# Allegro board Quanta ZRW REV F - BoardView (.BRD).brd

Outline 234.6 x 204.38 mm; copper layers: TOP, SVCC, IN1, IN2, SGND, BOTTOM. Coordinates in mm from the lower left corner of the outline.

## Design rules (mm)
constraint set DEFAULT: min track width 0.114
net group DFP-S3.5(4)W4.5(5)-T12B: nets VMA_RDQS4 VMA_WDQS4
net group DFP-S10W4.5(5)-T2B: nets VCORE_SENSE VCORESS_SENSE
net group W10-T12B: nets HDMI_5V RSET
net group W12-T12B: nets PCIE_RCOMPN PCIE_RCOMPP
net group W25-T12B: nets +3V_RTC VCCRTC_2
net group W50-T12B: nets +TPVDD +VDDQ_VTT
net group W60-T12B: nets LANVCC V_BLIGHT
net group W80-T12B: nets +5V_HDD +5V_ODD
net group DFP-S4.5W4.5(5)-T12B: nets M_A_DQS0 M_A_DQS1 M_A_DQS2 M_A_DQS3 M_A_DQS4 M_A_DQS5 M_A_DQS6 M_A_DQS7 M_A_DQS#0 M_A_DQS#1 M_A_DQS#2 M_A_DQS#3 M_A_DQS#4 M_A_DQS#5 M_A_DQS#6 M_A_DQS#7 M_B_DQS0 M_B_DQS1 M_B_DQS2 M_B_DQS3 M_B_DQS4 M_B_DQS5 M_B_DQS6 M_B_DQS7 M_B_DQS#0 M_B_DQS#1 M_B_DQS#2 M_B_DQS#3 M_B_DQS#4 M_B_DQS#5 M_B_DQS#6 M_B_DQS#7
net group DFP-S5W4.5(5)-2B: nets EDP_AUX#_C EDP_AUX_C EDP_AUXN EDP_AUXP EDP_TXN0 EDP_TXN0_C EDP_TXN1 EDP_TXN1_C EDP_TXP0 EDP_TXP0_C EDP_TXP1 EDP_TXP1_C
net group DFP-S5W4.5(5)-T2B: nets CRT_AUX#_C CRT_AUX_C CRT_AUXN_C CRT_AUXP CRT_AUXP_C CRT_TXN0 CRT_TXN0_C CRT_TXN1 CRT_TXN1_C CRT_TXP0 CRT_TXP0_C CRT_TXP1 CRT_TXP1_C DDCCLK DDCCLK_R DDCDAT DDCDAT_R INT_HDMICLK+ INT_HDMICLK+_C_R INT_HDMICLK- INT_HDMICLK-_C_R INT_HDMITX0N INT_HDMITX0N_C_R INT_HDMITX0P INT_HDMITX0P_C_R INT_HDMITX1N INT_HDMITX1N_C_R INT_HDMITX1P INT_HDMITX1P_C_R INT_HDMITX2N INT_HDMITX2N_C_R INT_HDMITX2P INT_HDMITX2P_C_R SATA_RXN0 SATA_RXN0_C SATA_RXN1 SATA_RXN1_C SATA_RXP0 SATA_RXP0_C SATA_RXP1 SATA_RXP1_C SATA_TXN0 SATA_TXN0_C SATA_TXN1 SATA_TXN1_C SATA_TXP0 SATA_TXP0_C SATA_TXP1 SATA_TXP1_C USB3_RXN0 USB3_RXN0_R USB3_RXN1 USB3_RXN1_R USB3_RXP0 USB3_RXP0_R USB3_RXP1 USB3_RXP1_R USB3_TXN0 USB3_TXN0_C USB3_TXN0_R USB3_TXN1 USB3_TXN1_C USB3_TXN1_R USB3_TXP0 USB3_TXP0_C USB3_TXP0_R USB3_TXP1 USB3_TXP1_C USB3_TXP1_R
net group DFP-S5W4.5(5)-T12B: nets 27M_XTAL_IN_R 27M_XTAL_OUT C_PEG_TX0 C_PEG_TX1 C_PEG_TX2 C_PEG_TX3 C_PEG_TX#0 C_PEG_TX#1 C_PEG_TX#2 C_PEG_TX#3 CLK_PCIE_LANN CLK_PCIE_LANP CLK_PCIE_WLANN CLK_PCIE_WLANP HDMI_DDCCLK_MB HDMI_DDCCLK_SW HDMI_DDCDATA_MB HDMI_DDCDATA_SW M_A_CLK0 M_A_CLK0# M_A_CLK1 M_A_CLK1# M_B_CLK0 M_B_CLK0# M_B_CLK1 M_B_CLK1# PCIE_RX5+_LAN PCIE_RX5-_LAN PCIE_RX6+_WLAN PCIE_RX6-_WLAN PCIE_TX5+ PCIE_TX5+_LAN PCIE_TX5- PCIE_TX5-_LAN PCIE_TX6+ PCIE_TX6+_WLAN PCIE_TX6- PCIE_TX6-_WLAN PEG_RX0 PEG_RX1 PEG_RX2 PEG_RX3 PEG_RX#0 PEG_RX#1 PEG_RX#2 PEG_RX#3 PEG_RXN0_C PEG_RXN1_C PEG_RXN2_C PEG_RXN3_C PEG_RXP0_C PEG_RXP1_C PEG_RXP2_C PEG_RXP3_C PEG_TX0 PEG_TX1 PEG_TX2 PEG_TX3 PEG_TX#0 PEG_TX#1 PEG_TX#2 PEG_TX#3 RTC_X1 RTC_X2 USBP0+ USBP0+_C USBP0+_R USBP0- USBP0-_C USBP0-_R USBP1+ USBP1+_R USBP1- USBP1-_R USBP3+ USBP3- USBP4+ USBP4- USBP5+ USBP5- USBP6+ USBP6+_R USBP6- USBP6-_R USBP7+ USBP7- XTAL1 XTAL2 XTAL24_IN XTAL24_OUT
net group DFP-S6W4.5(5)-T12B: nets 2ND_MBCLK 2ND_MBDATA GPUT_CLK_L I2C0_SCL I2C0_SDA I2C1_SCL I2C1_SCL_C I2C1_SDA I2C1_SDA_C I2C_TP_SCL_R I2C_TP_SDA_R MBCLK MBDATA N17046941 N17047425 PCH_MBCLK0_R PCH_MBDAT0_R TPCLK TPCLK_R TPDATA TPDATA_R
net group DFP-S18(13)W4.5(5)-T2B: nets INT_HDMICLK+_C INT_HDMICLK-_C INT_HDMITX0N_C INT_HDMITX0P_C INT_HDMITX1N_C INT_HDMITX1P_C INT_HDMITX2N_C INT_HDMITX2P_C
net group DFP-S18(13)W4.5(5)-T12B: nets LAN_MX0+ LAN_MX0- LAN_MX1+ LAN_MX1- LAN_MX2+ LAN_MX2- LAN_MX3+ LAN_MX3- MDI_0+ MDI_0- MDI_1+ MDI_1- MDI_2+ MDI_2- MDI_3+ MDI_3-
net group W4.5(5)-T2B: nets ACZ_SDIN H_PECI H_PROCHOT# HDA_BCLK_R HDA_RST#_R HDA_SDO_R HDA_SYNC_R PCH_AZ_CODEC_BITCLK PCH_AZ_CODEC_RST# PCH_AZ_CODEC_SDIN0 PCH_AZ_CODEC_SDOUT PCH_AZ_CODEC_SYNC
net group W4.5(5)-T12B: nets CATERR# CLK_PCI_EC CLK_PCI_LPC CLK_PCI_LPC_C CLK_PCIE_LAN_REQ# CLK_PCIE_REQ4# CLK_PCIE_REQ5# CRT_HPD DDR_VTTT_PG_CTRL DMIC_CLK_L DMIC_DAT_L DNBSWON# DPWROK_C DPWROK_R H_CPU_SVIDCLK H_CPU_SVIDDAT H_PROCHOT#_R HDMI_MB_HPD HP_DET_CN INT_HDMI_HPD INTRUDER# LPC_LAD0 LPC_LAD0_C LPC_LAD1 LPC_LAD1_C LPC_LAD2 LPC_LAD2_C LPC_LAD3 LPC_LAD3_C LPC_LFRAME# LPC_LFRAME#_C M_A_DQ0 M_A_DQ1 M_A_DQ2 M_A_DQ3 M_A_DQ4 M_A_DQ5 M_A_DQ6 M_A_DQ7 M_A_DQ8 M_A_DQ9 M_A_DQ10 M_A_DQ11 M_A_DQ12 M_A_DQ13 M_A_DQ14 M_A_DQ15 M_A_DQ16 M_A_DQ17 M_A_DQ18 M_A_DQ19 M_A_DQ20 M_A_DQ21 M_A_DQ22 M_A_DQ23 M_A_DQ24 M_A_DQ25 M_A_DQ26 M_A_DQ27 M_A_DQ28 M_A_DQ29 M_A_DQ30 M_A_DQ31 M_A_DQ32 M_A_DQ33 M_A_DQ34 M_A_DQ35 M_A_DQ36 M_A_DQ37 M_A_DQ38 M_A_DQ39 M_A_DQ40 M_A_DQ41 M_A_DQ42 M_A_DQ43 M_A_DQ44 M_A_DQ45 M_A_DQ46 M_A_DQ47 M_A_DQ48 M_A_DQ49 M_A_DQ50 M_A_DQ51 M_A_DQ52 M_A_DQ53 M_A_DQ54 M_A_DQ55 M_A_DQ56 M_A_DQ57 M_A_DQ58 M_A_DQ59 M_A_DQ60 M_A_DQ61 M_A_DQ62 M_A_DQ63 M_B_DQ0 M_B_DQ1 M_B_DQ2 M_B_DQ3 M_B_DQ4 M_B_DQ5 M_B_DQ6 M_B_DQ7 M_B_DQ8 M_B_DQ9 M_B_DQ10 M_B_DQ11 M_B_DQ12 M_B_DQ13 M_B_DQ14 M_B_DQ15 M_B_DQ16 M_B_DQ17 M_B_DQ18 M_B_DQ19 M_B_DQ20 M_B_DQ21 M_B_DQ22 M_B_DQ23 M_B_DQ24 M_B_DQ25 M_B_DQ26 M_B_DQ27 M_B_DQ28 M_B_DQ29 M_B_DQ30 M_B_DQ31 M_B_DQ32 M_B_DQ33 M_B_DQ34 M_B_DQ35 M_B_DQ36 M_B_DQ37 M_B_DQ38 M_B_DQ39 M_B_DQ40 M_B_DQ41 M_B_DQ42 M_B_DQ43 M_B_DQ44 M_B_DQ45 M_B_DQ46 M_B_DQ47 M_B_DQ48 M_B_DQ49 M_B_DQ50 M_B_DQ51 M_B_DQ52 M_B_DQ53 M_B_DQ54 M_B_DQ55 M_B_DQ56 M_B_DQ57 M_B_DQ58 M_B_DQ59 M_B_DQ60 M_B_DQ61 M_B_DQ62 M_B_DQ63 PCH_PWRBTN# PCH_RSMRST# PCH_SPI_CLK PCH_SPI_CLK_EC PCH_SPI_CS0# PCH_SPI_SI PCH_SPI_SI_EC PCH_SPI_SO PCH_SPI_SO_EC PCI_PLTRST# PCIE_CLKREQ_WLAN# PCLK_TPM PEGX_RST# PEX_TERMP PLTRST# RSMRST# RTC_RST# SD_CDZ SD_CLK SD_CLK_R SD_CMD SD_D0/MS_D6 SD_D1/MS_D7 SD_D2/MS_D5 SD_D3/MS_D4 SD_WP/MS_D1 SIO_RCIN# SPI_CLK_8M SPI_CS0#_UR_ME SPI_SI_8M SPI_SO_8M SRTC_RST# SYS_PWROK SYS_PWROK_R SYS_RESET# TESTMODE THRMTRIP# USBCOMP VCCST_PWRGD VR_SVID_ALERT#_VCORE XD_CD# XDP_BPM#0 XDP_BPM#1
net group W4.5-TB: nets CRT_B1 CRT_BLU CRT_G1 CRT_GRE CRT_R1 CRT_RED CRTHSYNC CRTVSYNC HSYNC VSYNC
net group W5(6.5)-T12B: nets FBA_CMD0 FBA_CMD1 FBA_CMD2 FBA_CMD3 FBA_CMD4 FBA_CMD5 FBA_CMD6 FBA_CMD7 FBA_CMD8 FBA_CMD9 FBA_CMD10 FBA_CMD11 FBA_CMD12 FBA_CMD13 FBA_CMD14 FBA_CMD15 FBA_CMD16 FBA_CMD17 FBA_CMD18 FBA_CMD19 FBA_CMD20 FBA_CMD21 FBA_CMD22 FBA_CMD23 FBA_CMD24 FBA_CMD25 FBA_CMD26 FBA_CMD27 FBA_CMD28 FBA_CMD29 FBA_CMD30 VMA_DM0 VMA_DM1 VMA_DM2 VMA_DM3 VMA_DM4 VMA_DM5 VMA_DM6 VMA_DM7 VMA_DQ0 VMA_DQ1 VMA_DQ2 VMA_DQ3 VMA_DQ4 VMA_DQ5 VMA_DQ6 VMA_DQ7 VMA_DQ8 VMA_DQ9 VMA_DQ10 VMA_DQ11 VMA_DQ12 VMA_DQ13 VMA_DQ14 VMA_DQ15 VMA_DQ16 VMA_DQ17 VMA_DQ18 VMA_DQ19 VMA_DQ20 VMA_DQ21 VMA_DQ22 VMA_DQ23 VMA_DQ24 VMA_DQ25 VMA_DQ26 VMA_DQ27 VMA_DQ28 VMA_DQ29 VMA_DQ30 VMA_DQ31 VMA_DQ32 VMA_DQ33 VMA_DQ34 VMA_DQ35 VMA_DQ36 VMA_DQ37 VMA_DQ38 VMA_DQ39 VMA_DQ40 VMA_DQ41 VMA_DQ42 VMA_DQ43 VMA_DQ44 VMA_DQ45 VMA_DQ46 VMA_DQ47 VMA_DQ48 VMA_DQ49 VMA_DQ50 VMA_DQ51 VMA_DQ52 VMA_DQ53 VMA_DQ54 VMA_DQ55 VMA_DQ56 VMA_DQ57 VMA_DQ58 VMA_DQ59 VMA_DQ60 VMA_DQ61 VMA_DQ62 VMA_DQ63
net group W6.5(8.5)-T12B: nets M_A_A0 M_A_A1 M_A_A2 M_A_A3 M_A_A4 M_A_A5 M_A_A6 M_A_A7 M_A_A8 M_A_A9 M_A_A10 M_A_A11 M_A_A12 M_A_A13 M_A_A14 M_A_A15 M_A_BS#0 M_A_BS#1 M_A_BS#2 M_A_CAS# M_A_CKE0 M_A_CKE1 M_A_CS#0 M_A_CS#1 M_A_ODT0_DIMM M_A_ODT1_DIMM M_A_RAS# M_A_WE# M_B_A0 M_B_A1 M_B_A2 M_B_A3 M_B_A4 M_B_A5 M_B_A6 M_B_A7 M_B_A8 M_B_A9 M_B_A10 M_B_A11 M_B_A12 M_B_A13 M_B_A14 M_B_A15 M_B_BS#0 M_B_BS#1 M_B_BS#2 M_B_CAS# M_B_CKE0 M_B_CKE1 M_B_CS#0 M_B_CS#1 M_B_ODT0_DIMM M_B_ODT1_DIMM M_B_RAS# M_B_WE#
net group W15-T12B: nets FB_CAL_PD_VDDQ HP-L2 HP-L3 HP-R2 HP-R3 HP_JD# LINE1-L LINE1-R LINE1-VREFO-L LINE1-VREFO-R MIC2-VREFO SENSEA SM_RCOMP_0 SM_RCOMP_1 SM_RCOMP_2 SP_PLLVDD
net group W20-T12B: nets +1.5VA +3V_CR +3V_MAIN +3V_S5 +5VA +AZA_VDD +FB_PLLAVDD +VCCPDSW_3P3 +VREF_CA_CPU +VREFDQ_SA_M3 +VREFDQ_SB_M3 +WL_VDD CFG_RCOMP DAC_VDDC DVDD_IO EDP_RCOMP FB_CAL_TERM_GND PEX_PLLVDD SLEEVE_R VCC_XD VREFC_VMA1 VREFC_VMA3 VREFD_VMA3
net group W30-T12B: nets +3V_EC +3VPCU_EC +3VPCU_ECPLL +5V_KB +5V_KB_R +A3VPCU +SMDDR_VREF_DQ0 +SMDDR_VREF_DQ1 +VDDQ CCD_PWR CRTVDD5 ECAGND IVDDO LAN_MCT0 LAN_MCT1 LAN_MCT2 LAN_MCT3 RING2_R TERM9 TH_FAN_POWER TP_PWR
net group W40-T12B: nets +SMDDR_VREF_DIMM L_SPK+ L_SPK+_1 L_SPK- L_SPK-_1 LCDVCC R_SPK+ R_SPK+_1 R_SPK- R_SPK-_1 REGOUT RING2 SLEEVE VDD10
net group W99-T12B: nets USBPWR1

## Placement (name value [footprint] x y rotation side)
BT1  bat_conn  [BAT-AP-AAA-BAT-054-K01-2P-SMT]  77.82 65.66 0 bottom
C2  .1u/16v_4  [CC0402]  131.05 194.71 180 bottom
C4  .1u/16v_4  [CC0402]  131.05 193.7 180 bottom
C7  4.7u/25v_8  [CC0805]  129.12 195.58 180 top
C8  .1u/16v_4  [CC0402]  133.82 197.02 180 bottom
C9  1000p/50v_4  [CC0402]  128.1 193.92 0 top
C10  .1u/16v_4  [CC0402]  133.82 196.01 180 bottom
C11  dr@0.1u/16v_4  [CC0402]  176.26 192.6 0 top
C12  .1u/16v_4  [CC0402]  135.78 198.95 90 bottom
C13  .1u/16v_4  [CC0402]  134.76 198.95 90 bottom
C14  dr@1u/6.3v_4  [CC0402]  180 191.31 90 top
C15  ev@0.1u/16v_4  [CC0402]  182.28 191.31 90 top
C16  1000p/50v_4  [CC0402]  129.37 191.26 180 top
C17  *120p/50v_4  [CC0402]  190.72 191.26 270 top
C18  dr@0.1u/16v_4  [CC0402]  191.86 191.26 270 top
C19  dr@0.1u/16v_4  [CC0402]  193 191.26 270 top
C20  dr@1u/6.3v_4  [CC0402]  194.14 191.26 90 top
C21  dr@10u/6.3v_6  [CC0603]  195.29 191.26 270 top
C22  dr@1u/6.3v_4  [CC0402]  178.93 191.21 90 top
C23  dr@0.1u/16v_4  [CC0402]  177.79 191.18 90 top
C24  dr@1u/6.3v_4  [CC0402]  196.56 191.13 90 top
C25  dr@0.1u/16v_4  [CC0402]  197.57 191.13 270 top
C26  dr@10u/6.3v_6  [CC0603]  199.1 190.95 270 top
C27  0.1u/10v_4_x7r  [CC0402]  129.37 190.24 180 top
C28  dr@0.1u/16v_4  [CC0402]  167.65 189.51 0 top
C29  *2.2u/10v_8  [CC0805]  120.1 188.21 90 top
C30  22u/6.3v_8  [CC0805]  122.14 188.21 270 top
C31  dr@0.1u/16v_4  [CC0402]  167.63 188.03 180 top
C32  dr@4.7u/10v_6  [CC0603]  167.32 186.3 0 top
C33  *0.1u/16v_4  [CC0402]  120.23 185.29 270 top
C34  0.01u/50v_4  [CC0402]  121.37 185.29 90 top
C35  0.1u/16v_4  [CC0402]  122.39 185.29 270 top
C36  dr@4.7u/10v_6  [CC0603]  207.63 184.91 180 top
C37  ev@0.01u/25v_4  [CC0402]  166.94 184.27 90 top
C38  ev@1u/6.3v_4  [CC0402]  207.61 183.64 0 top
C39  dr@1u/6.3v_4  [CC0402]  207.61 182.49 0 top
C40  ev@4.7u/10v_6  [CC0603]  207.73 181.22 180 top
C41  1u/6.3v_4  [CC0402]  116.42 181.1 0 top
C42  dr@1u/6.3v_4  [CC0402]  168.11 180.18 270 top
C43  ev@0.1u/16v_4  [CC0402]  167.55 178.18 0 top
C44  dr@0.1u/16v_4  [CC0402]  203.29 177.92 180 top
C45  dr@0.1u/16v_4  [CC0402]  167.6 176.93 0 top
C46  *120p/50v_4  [CC0402]  167.63 175.76 0 top
C47  ev@10u/6.3v_6  [CC0603]  167.32 174.44 0 top
C48  ev@0.1u/16v_4  [CC0402]  167.63 173.2 180 top
C49  dr@10u/6.3v_6  [CC0603]  194.4 173.1 90 top
C50  dr@10u/6.3v_6  [CC0603]  195.67 173.1 90 top
C51  dr@0.1u/16v_4  [CC0402]  193.13 172.97 90 top
C52  ev@4.7u/10v_6  [CC0603]  191.22 172.33 180 top
C53  dr@0.1u/16v_4  [CC0402]  174.38 172.31 180 top
C54  ev@4.7u/10v_6  [CC0603]  176.85 172.26 180 top
C55  dr@4.7u/10v_6  [CC0603]  167.35 172.03 0 top
C56  dr@0.1u/16v_4  [CC0402]  178.7 171.85 90 top
C57  dr@0.1u/16v_4  [CC0402]  183.98 171.83 270 top
C58  dr@0.1u/16v_4  [CC0402]  185.15 171.83 270 top
C59  dr@10u/6.3v_6  [CC0603]  196.18 170.43 0 top
C60  dr@1u/6.3v_4  [CC0402]  196.43 169.16 180 top
C61  dr@1u/6.3v_4  [CC0402]  190.84 169.03 270 top
C62  ev@0.1u/16v_4  [CC0402]  192.11 169.03 270 top
C63  ev@4.7u/10v_6  [CC0603]  173.77 168.02 90 top
C64  ev@22u/6.3vs_6  [CC0603]  172.02 167.97 270 top
C65  *10u/10v_6  [CC0603]  170.32 167.94 90 top
C66  dr@0.1u/16v_4  [CC0402]  188.05 167.51 270 top
C67  *120p/50v_4  [CC0402]  189.19 167.51 90 top
C68  dr@0.1u/16v_4  [CC0402]  183.22 167.38 270 top
C69  ev@4.7u/10v_6  [CC0603]  175.98 167.18 180 top
C70  ev@0.1u/16v_4  [CC0402]  197.07 165.22 270 top
C71  ev@0.1u/16v_4  [CC0402]  175.73 163.83 180 top
C72  ev@22u/6.3vs_6  [CC0603]  170.79 163.1 0 top
C73  ev@4.7u/10v_6  [CC0603]  184.56 162.7 270 top
C74  ev@1u/10v_6  [CC0603]  185.83 162.7 270 top
C75  dr@4.7u/10v_6  [CC0603]  177 162.51 0 top
C76  ev@0.1u/16v_4  [CC0402]  187.99 162.45 270 top
C77  ev@0.1u/16v_4  [CC0402]  186.96 162.43 90 top
C78  ev@4.7u/10v_6  [CC0603]  170.79 161.83 180 top
C79  ev@22u/6.3vs_6  [CC0603]  168.62 161.46 90 top
C80  ev@4.7u/10v_6  [CC0603]  167.35 161.41 90 top
C81  ev@0.1u/16v_4  [CC0402]  195.69 161.08 180 top
C82  ev@0.1u/16v_4  [CC0402]  187.59 160.88 180 top
C83  ev@22u/6.3v_8  [CC0805]  182.85 160.79 270 top
C84  ev@10u/6.3v_6  [RC0603]  177 160.78 180 top
C85  ev@330u_2.5v_3528  [CC3528]  180.15 160.4 270 top
C86  ev@4.7u/10v_6  [CC0603]  185 160.07 90 top
C87  *22u/6.3vs_6  [CC0603]  170.8 159.76 0 top
C88  ev@1u/6.3v_4  [CC0402]  176.87 159.63 180 top
C89  ev@0.1u/16v_4  [CC0402]  187.5 159.52 180 top
C90  ev@4.7u/10v_6  [CC0603]  170.8 158.42 180 top
C91  ev@1u/6.3v_4  [CC0402]  174.73 158.4 180 top
C92  ev@0.1u/16v_4  [CC0402]  176.78 158.38 180 top
C93  ev@4.7u/10v_6  [CC0603]  183.35 157.98 180 top
C94  dr@4.7u/10v_6  [CC0603]  196.3 157.98 0 top
C95  ev@1u/10v_6  [CC0603]  187.79 157.6 90 top
C96  ev@1u/6.3v_4  [CC0402]  176.87 156.97 0 top
C97  ev@1u/6.3v_4  [CC0402]  174.73 156.88 180 top
C98  ev@1u/6.3v_4  [CC0402]  198.59 156.71 270 top
C99  dr@1u/6.3v_4  [CC0402]  199.73 156.71 270 top
C100  dr@0.1u/16v_4  [CC0402]  200.88 156.71 270 top
C101  ev@0.1u/16v_4  [CC0402]  202.02 156.71 90 top
C102  dr@1u/6.3v_4  [CC0402]  203.16 156.71 270 top
C103  dr@0.1u/16v_4  [CC0402]  205.7 156.71 90 top
C104  ev@0.1u/16v_4  [CC0402]  212.69 156.71 90 top
C105  *120p/50v_4  [CC0402]  213.83 156.71 90 top
C106  dr@1u/6.3v_4  [CC0402]  214.97 156.71 270 top
C107  dr@0.1u/16v_4  [CC0402]  216.12 156.71 90 top
C108  dr@1u/6.3v_4  [CC0402]  217.26 156.71 270 top
C109  ev@4.7u/10v_6  [CC0603]  181.19 156.59 180 top
C110  dr@4.7u/10v_6  [CC0603]  204.43 156.46 90 top
C111  ev@4.7u/10v_6  [CC0603]  170.83 156.28 180 top
C112  ev@4.7u/10v_6  [CC0603]  186.14 156.21 270 top
C113  ev@4.7u/10v_6  [CC0603]  183.1 156.08 90 top
C114  10u/6.3v_4  [CC0402]  153.89 155.95 270 top
C115  ev@0.01u/25v_4  [CC0402]  219.04 155.95 180 top
C116  ev@4.7u/10v_6  [CC0603]  178.9 155.32 270 top
C117  ev@0.1u/16v_4  [CC0402]  187.79 155.24 270 top
C118  ev@4.7u/10v_6  [CC0603]  184.87 155.19 270 top
C119  ev@1u/6.3v_4  [CC0402]  176.94 155.08 90 top
C120  ev@4.7u/10v_6  [CC0603]  181.19 154.81 180 top
C121  ev@1u/6.3v_4  [CC0402]  175.86 154.3 270 top
C122  dr@0.1u/16v_4  [CC0402]  212.31 154.3 0 top
C123  ev@4.7u/10v_6  [CC0603]  184.37 153.28 180 top
C124  ev@0.1u/16v_4  [CC0402]  186.91 153.28 0 top
C125  ev@1u/6.3v_4  [CC0402]  182.51 153.16 270 top
C126  ev@4.7u/10v_6  [CC0603]  178.14 152.9 180 top
C127  ev@0.1u/16v_4  [CC0402]  186.91 152.14 0 top
C128  ev@1u/6.3v_4  [CC0402]  178.52 151.76 180 top
C129  ev@0.1u/16v_4  [CC0402]  183.78 151.35 90 top
C130  ev@1u/6.3v_4  [CC0402]  180.81 150.97 0 top
C131  ev@0.1u/16v_4  [CC0402]  173.82 150.62 180 top
C132  ev@4.7u/10v_6  [CC0603]  176.24 150.62 180 top
C133  ev@0.1u/16v_4  [CC0402]  185.51 150.49 0 top
C134  *0.1u/16v_4  [CC0402]  167.67 149.75 0 top
C135  ev@4.7u/10v_6  [CC0603]  173.57 149.47 0 top
C136  *0.1u/16v_4  [CC0402]  159.22 149.22 90 top
C137  ev@1u/10v_6  [CC0603]  187.57 149.14 0 top
C138  ev@1u/10v_6  [CC0603]  191.24 149.13 180 top
C139  *1000p/50v_4  [CC0402]  166.08 148.97 270 top
C140  ev@4.7u/6.3vs_6  [CC0603]  178.66 148.88 180 top
C141  ev@1000p/50v_4  [CC0402]  171.06 148.51 180 top
C142  ev@22u/6.3vs_6  [CC0603]  182.44 148.38 180 top
C143  ev@4.7u/10v_6  [CC0603]  187.57 147.93 0 top
C144  47u/6.3v_8  [CC0805]  147.82 147.85 180 top
C145  ev@4.7u/10v_6  [CC0603]  191.25 147.82 180 top
C146  ev@4.7u/6.3vs_6  [CC0603]  178.66 147.61 180 top
C147  ev@1000p/50v_4  [CC0402]  163.56 147.19 0 top
C148  10u/6.3v_4  [CC0402]  126.96 146.68 180 top
C149  ev@4.7u/6.3vs_6  [CC0603]  178.66 146.34 180 top
C150  47u/6.3v_8  [CC0805]  147.82 145.82 180 top
C151  10u/6.3v_4  [CC0402]  126.96 145.66 180 top
C152  ev@4.7u/10v_6  [CC0603]  182.47 144.94 180 top
C153  ev@47u/6.3v_8  [CC0805]  178.28 144.68 180 top
C154  ev@22u/6.3vs_6  [CC0603]  185.7 144.16 0 top
C155  10u/6.3v_4  [CC0402]  126.96 144.14 180 top
C156  ev@0.1u/16v_4  [CC0402]  182.22 143.8 180 top
C157  10u/6.3v_4  [CC0402]  146.27 142.11 0 top
C158  10u/6.3v_4  [CC0402]  126.96 143.12 180 top
C159  ev@22u/6.3v_8  [CC0805]  178.28 142.65 180 top
C160  ev@4.7u/6.3vs_6  [CC0603]  181.33 142.53 0 top
C161  10u/6.3v_4  [CC0402]  126.96 142.11 180 top
C162  *1000p/50v_4  [CC0402]  164.3 141.98 180 top
C163  ev@4.7u/6.3vs_6  [CC0603]  181.33 141.26 0 top
C164  0.1u/16v_4  [CC0402]  195.77 91.54 180 top
C165  10u/6.3v_4  [CC0402]  155.79 142.24 90 top
C166  gt@0.022u/25v_4  [CC0402]  207.86 140.25 0 top
C167  gt@0.022u/25v_4  [CC0402]  207.86 139.19 0 top
C168  *0.1u/16v_4  [CC0402]  158.46 139.31 90 top
C169  kbl@4.7u/10v_6  [CC0603]  213.7 137.92 90 top
C170  kbl@0.01u/50v_4  [CC0402]  212.56 137.54 90 top
C171  22u/6.3v_6  [CC0603]  120.61 137.16 270 top
C172  1u/6.3v_4  [CC0402]  149.59 134.62 180 bottom
C173  1u/6.3v_4  [CC0402]  155.61 130.02 270 top
C174  1u/6.3v_4  [CC0402]  152.23 131.57 0 top
C175  gt@0.1u/16v_4  [CC0402]  194.73 134.08 270 top
C176  1u/6.3v_4  [CC0402]  152.23 132.58 0 top
C177  gt@0.1u/16v_4  [CC0402]  170.78 133.73 180 top
C178  22u/6.3v_6  [CC0603]  120.1 132.33 90 top
C179  1u/6.3v_4  [CC0402]  156.63 130.02 270 top
C180  ev@0.1u/16v_4  [CC0402]  177.38 132.08 0 top
C181  1u/6.3v_2  [CC0201]  135.22 129.1 0 top
C182  47u/6.3v_8  [CC0805]  160.77 130.91 180 top
C184  1u/6.3v_2  [CC0201]  131.03 122.93 180 top
C185  10u/6.3v_4  [CC0402]  116.8 130.55 270 top
C186  10u/6.3v_4  [CC0402]  117.82 130.55 270 top
C187  kbl@2.2u/6.3v_6  [CC0603]  212.69 130.55 180 top
C188  1u/6.3v_2  [CC0201]  119.85 128.9 90 top
C189  1u/6.3v_2  [CC0201]  135.22 130.07 0 top
C190  47u/6.3v_8  [CC0805]  105.37 130.04 180 top
C191  1u/6.3v_4  [CC0402]  162.52 129.28 0 top
C192  1u/6.3v_4  [CC0402]  154.14 129.66 270 top
C193  1u/6.3v_2  [CC0201]  118.83 128.77 90 top
C194  1u/6.3v_2  [CC0201]  116.8 128.77 90 top
C195  1u/6.3v_2  [CC0201]  117.82 128.77 90 top
C196  1u/6.3v_2  [CC0201]  137.27 131.06 180 top
C197  1u/6.3v_2  [CC0201]  116.8 125.34 270 top
C198  1u/6.3v_2  [CC0201]  117.82 125.34 270 top
C199  47u/6.3v_8  [CC0805]  105.37 128.04 180 top
C200  1u/6.3v_2  [CC0201]  138.39 129.08 180 top
C201  1u/6.3v_2  [CC0201]  138.9 126.67 180 top
C202  47u/6.3v_6  [CC0603]  130.54 120.65 0 top
C203  22u/6.3v_6  [CC0603]  138.62 117.9 0 top
C204  1u/6.3v_2  [CC0201]  116.93 123.82 90 top
C205  1u/6.3v_2  [CC0201]  115.79 125.34 270 top
C206  1u/6.3v_2  [CC0201]  115.79 127.5 270 top
C207  1u/6.3v_2  [CC0201]  140.17 125.98 0 top
C209  1u/6.3v_2  [CC0201]  138.77 125.7 180 top
C210  47u/6.3v_6  [CC0603]  130.54 119.48 0 top
C212  1u/6.3v_2  [CC0201]  131.79 123.95 180 top
C214  1u/6.3v_2  [CC0201]  138.52 115.31 180 top
C215  1u/6.3v_2  [CC0201]  144.36 157.35 270 top
C216  1u/6.3v_2  [CC0201]  140.98 124.58 0 top
C217  1u/6.3v_4  [CC0402]  160.64 124.41 90 top
C218  10u/6.3v_4  [CC0402]  105.5 124.18 0 top
C219  22u/6.3v_6  [CC0603]  138.65 123.47 0 top
C221  10u/6.3v_4  [CC0402]  141.19 123.57 0 top
C222  1u/6.3v_2  [CC0201]  145.5 157.35 270 top
C223  10u/6.3v_4  [CC0402]  105.5 123.16 0 top
C224  22u/6.3v_6  [CC0603]  133.87 123.08 180 top
C225  *1u/6.3v_4  [CC0402]  161.66 122.93 270 top
C226  22u/6.3v_6  [CC0603]  138.65 124.63 0 top
C227  1u/6.3v_2  [CC0201]  147.99 147.9 90 bottom
C228  1u/6.3v_2  [CC0201]  146.52 157.35 270 top
C229  10u/6.3v_4  [CC0402]  141.19 122.55 0 top
C230  1u/6.3v_4  [CC0402]  160.62 122.35 270 top
C232  10u/6.3v_4  [CC0402]  105.5 122.14 0 top
C233  22u/6.3v_6  [CC0603]  133.87 121.84 180 top
C235  1u/6.3v_2  [CC0201]  145.96 147.9 90 bottom
C236  22u/6.3v_6  [CC0603]  133.85 124.38 180 top
C237  1u/6.3v_2  [CC0201]  133.57 118.36 0 top
C238  10u/6.3v_4  [CC0402]  141.19 121.41 0 top
C239  1u/6.3v_2  [CC0201]  116.8 127.5 270 top
C240  1u/6.3v_2  [CC0201]  117.82 127.5 270 top
C241  1u/6.3v_2  [CC0201]  118.83 127.5 270 top
C242  1u/6.3v_2  [CC0201]  143.19 120.93 180 top
C243  22u/6.3v_6  [CC0603]  133.87 120.62 180 top
C245  1u/6.3v_2  [CC0201]  146.98 147.9 90 bottom
C246  1u/6.3v_2  [CC0201]  135.95 115.31 0 top
C247  10u/6.3v_4  [CC0402]  141.19 120.39 0 top
C248  47u/6.3v_8  [CC0805]  112.99 122.8 270 top
C249  1u/6.3v_2  [CC0201]  143.47 119.96 180 top
C250  1u/6.3v_4  [CC0402]  158.89 119.83 0 top
C251  22u/6.3v_6  [CC0603]  138.62 119.1 0 top
C252  1u/6.3v_2  [CC0201]  142.68 143.51 180 bottom
C254  10u/6.3v_4  [CC0402]  141.19 119.38 0 top
C255  22u/6.3v_6  [CC0603]  133.87 119.45 180 top
C256  1u/6.3v_4  [CC0402]  166.66 119.88 90 top
C257  10u/6.3v_4  [CC0402]  138.82 121.2 180 top
C258  10u/6.3v_4  [CC0402]  137.43 130.07 180 top
C259  10u/6.3v_4  [CC0402]  138.82 120.19 180 top
C260  1u/6.3v_2  [CC0201]  143.47 118.99 180 top
C261  1u/6.3v_4  [CC0402]  176.36 118.64 270 top
C262  1u/6.3v_2  [CC0201]  142.68 142.49 180 bottom
C263  10u/6.3v_4  [CC0402]  141.19 118.36 0 top
C264  1u/6.3v_2  [CC0201]  132.19 117.98 270 top
C265  *1u/6.3v_4  [CC0402]  159.91 118.08 90 top
C266  1u/6.3v_2  [CC0201]  131.23 117.98 270 top
C267  1u/6.3v_2  [CC0201]  143.47 118.03 180 top
C268  1u/6.3v_4  [CC0402]  170.78 117.34 90 top
C269  1u/6.3v_2  [CC0201]  137.25 115.31 0 top
C270  *1u/6.3v_4  [CC0402]  166.46 118.26 0 top
C272  22u/6.3v_6  [CC0603]  138.65 122.3 0 top
C273  22u/6.3v_6  [CC0603]  138.21 127.73 0 top
C274  22u/6.3v_6  [CC0603]  114.64 123.29 270 top
C275  22u/6.3v_6  [CC0603]  115.81 123.29 270 top
C276  gt3@22u/6.3v_6  [CC0603]  130.72 115.24 270 top
C277  22u/6.3v_6  [CC0603]  131.28 121.84 0 top
C278  1u/6.3v_2  [CC0201]  143.47 117.01 180 top
C279  gt3@10u/6.3v_4  [CC0402]  130.24 117.57 270 top
C280  gt3@10u/6.3v_4  [CC0402]  128.21 117.57 270 top
C281  gt3@10u/6.3v_4  [CC0402]  129.22 117.57 270 top
C282  22u/6.3v_6  [CC0603]  133.85 126.39 180 top
C283  10u/6.3v_4  [CC0402]  140.42 116.79 270 top
C284  10u/6.3v_4  [CC0402]  141.44 116.79 270 top
C285  1u/6.3v_2  [CC0201]  138.93 116.84 180 top
C286  10u/6.3v_4  [CC0402]  133.57 116.45 270 top
C288  10u/6.3v_4  [CC0402]  143.47 115.08 180 top
C289  22u/6.3v_6  [CC0603]  134.73 114.14 270 top
C290  gt3@10u/6.3v_4  [CC0402]  127.04 115.18 180 top
C291  gt3@10u/6.3v_4  [CC0402]  129.07 115.18 0 top
C292  *1u/6.3v_4  [CC0402]  169.13 115.31 180 top
C297  1u/6.3v_2  [CC0201]  140.73 115.06 270 top
C298  1u/6.3v_2  [CC0201]  141.82 115.06 180 top
C299  1u/6.3v_2  [CC0201]  133.52 114.96 180 top
C300  *220p/50v_4  [CC0402]  7.96 113.79 90 top
C301  0.1u/16v_4  [CC0402]  9.11 113.79 270 top
C302  gt3@22u/6.3v_6  [CC0603]  110.07 120.26 270 top
C303  gt3@22u/6.3v_6  [CC0603]  111.34 120.26 270 top
C304  *0.1u/16v_4  [CC0402]  7.96 111.76 270 top
C305  *0.22u/6.3v_4  [CC0402]  9.11 111.76 90 top
C306  *0.1u/16v_4  [CC0402]  27.14 111.63 0 top
C307  gt3@22u/6.3v_6  [CC0603]  105.63 118.23 180 top
C308  1u/6.3v_2  [CC0201]  142.71 110.87 90 top
C309  0.1u/16v_4  [CC0402]  27.14 110.61 0 top
C310  gt3@22u/6.3v_6  [CC0603]  110.45 116.45 0 top
C311  1u/6.3v_2  [CC0201]  138.14 110.36 270 top
C312  1u/6.3v_2  [CC0201]  134.71 110.23 270 top
C313  1u/6.3v_2  [CC0201]  135.85 110.23 90 top
C314  *0.1u/16v_4  [CC0402]  167.58 110.23 0 top
C315  0.1u/16v_4  [CC0402]  27.77 109.47 180 top
C316  gt3@10u/6.3v_4  [CC0402]  123.53 109.47 270 top
C317  gt3@10u/6.3v_4  [CC0402]  124.55 109.47 270 top
C318  10u/6.3v_4  [CC0402]  133.18 109.47 180 top
C319  5.6p/16v_4  [CC0402]  11.52 109.17 90 top
C320  5.6p/16v_4  [CC0402]  15.28 109.17 90 top
C321  2.2u_6  [CC0603]  55.71 109.09 0 top
C322  1u/6.3v_4  [CC0402]  147.66 109.09 270 top
C323  10u/6.3v_4  [CC0402]  144.11 108.96 270 top
C324  gt3@10u/6.3v_4  [CC0402]  125.69 109.09 90 top
C325  10u/6.3v_4  [CC0402]  127.47 108.58 0 top
C326  10u/6.3v_4  [CC0402]  135.98 108.58 0 top
C327  10u/6.3v_4  [CC0402]  141.69 108.58 180 top
C328  10u/6.3v_4  [CC0402]  138.52 108.56 180 top
C329  0.1u/16v_4  [CC0402]  27.77 108.45 180 top
C330  *15p/50v_4  [CC0402]  227.16 108.33 270 top
C331  0.1u/16v_4  [CC0402]  27.77 107.31 180 top
C332  0.1u/16v_4  [CC0402]  168.62 106.93 180 top
C333  5.6p/16v_4  [CC0402]  11.52 107.13 270 top
C334  5.6p/16v_4  [CC0402]  15.28 107.13 270 top
C335  0.1u/16v_4  [CC0402]  27.77 106.29 180 top
C336  5.6p/16v_4  [CC0402]  11.52 105.1 270 top
C337  5.6p/16v_4  [CC0402]  15.28 105.1 270 top
C338  **0.1u/16v_4  [CC0402]  186.14 104.64 90 top
C339  **0.1u/16v_4  [CC0402]  187.29 104.64 90 top
C340  10u/6.3v_6  [CC0603]  188.43 104.52 270 top
C341  0.1u/16v_4  [CC0402]  25.49 104.39 180 top
C342  10u/6.3v_6  [CC0603]  18.2 103.7 90 top
C343  0.1u/16v_4  [CC0402]  25.49 103.37 180 top
C344  *ioac@1000p/50v_4  [CC0402]  179.97 102.1 0 top
C345  *ioac@0.1u/16v_4  [CC0402]  182.08 102.1 180 top
C346  *0.1u/16v_4  [CC0402]  185.38 102.1 270 top
C347  *10u/6.3v_6  [CC0603]  184.24 101.85 90 top
C348  0.1u/16v_4  [CC0402]  168.59 94.92 180 top
C349  1u/6.3v_4  [CC0402]  168.59 95.93 0 top
C350  *0.1u/16v_4  [CC0402]  30.06 93.98 180 top
C351  6.8p/50v_4  [CC0402]  158.08 93.21 90 top
C352  0.1u/16v_4  [CC0402]  162.78 93.09 270 top
C353  0.1u/16v_4  [CC0402]  202.02 92.93 0 top
C354  0.1u/16v_4  [CC0402]  30.06 92.83 0 top
C355  0.1u/16v_4  [CC0402]  32.35 92.58 270 top
C356  10u/6.3v_4  [CC0402]  203.54 92.45 90 top
C357  *10p/50v_4  [CC0402]  206.72 92.45 270 top
C358  12p/50v_4  [CC0402]  34.76 92.07 0 top
C359  12p/50v_4  [CC0402]  36.79 92.07 180 top
C360  10p/50v_4  [CC0402]  202.02 91.92 0 top
C361  4.7u/6.3v_6  [CC0603]  30.31 91.56 180 top
C362  6.8p/50v_4  [CC0402]  158.08 91.18 270 top
C363  0.1u/16v_4  [CC0402]  40.35 90.55 0 top
C364  0.01u/50v/x7r_4  [CC0402]  28.03 90.29 90 top
C365  4.7u/6.3v_6  [CC0603]  30.31 90.29 180 top
C366  10u/6.3v_6  [CC0603]  42 89.78 270 top
C367  0.1u/16v_4  [CC0402]  39.97 88.9 90 top
C368  *ioac@1000p/50v_4  [CC0402]  46.32 88.9 0 top
C369  *ioac@0.1u/16v_4  [CC0402]  48.35 88.9 180 top
C370  0.1u/16v_4  [CC0402]  44.03 88.77 180 top
C371  *0.1u/16v_4  [CC0402]  88.86 86.86 180 top
C372  0.1u/16v_4  [CC0402]  41.11 86.23 180 top
C373  *10u/6.3v_4  [CC0402]  88.86 85.85 180 top
C374  *10p/50v_4  [CC0402]  210.91 86.74 180 top
C375  0.1u/16v_4  [CC0402]  41.11 85.21 180 top
C376  *10p/50v_4  [CC0402]  88.86 84.83 180 top
C377  *0.1u/16v_4  [CC0402]  34.76 82.04 180 top
C378  *10p/50v_4  [CC0402]  80.99 79.37 90 top
C379  *10p/50v_4  [CC0402]  83.02 79.37 90 top
C380  1u/6.3v_4  [CC0402]  82.89 75.43 270 top
C381  1u/6.3v_4  [CC0402]  83.91 75.43 270 top
C382  1u/6.3v_4  [CC0402]  85.31 75.43 270 top
C383  *220p/50v_4  [CC0402]  14.06 74.72 270 top
C384  0.1u/16v_4  [CC0402]  20.79 73.91 270 top
C385  0.1u/16v_4  [CC0402]  26.89 73.91 270 top
C386  0.1u/16v_4  [CC0402]  27.9 73.91 270 top
C387  0.1u/16v_4  [CC0402]  29.68 72.69 0 top
C388  2.2u/6.3v_6  [CC0603]  164.81 71.98 180 top
C389  0.1u/16v_4  [CC0402]  29.68 71.57 0 top
C390  0.1u/16v_4  [CC0402]  162.9 71.35 270 top
C391  470p/50v_4  [CC0402]  96.48 70.33 90 top
C392  2.2u/6.3v_6  [CC0603]  98.64 70.33 270 top
C393  0.1u/16v_4  [CC0402]  99.78 70.33 270 top
C394  4.7u/10v_6  [CC0603]  168.11 69.69 90 top
C395  1u/6.3v_4  [CC0402]  165.95 69.44 270 top
C396  1u/6.3v_4  [CC0402]  166.97 69.44 270 top
C397  0.022u/16v_4  [CC0402]  92.72 69.36 270 top
C398  0.1u/16v_4  [CC0402]  29.68 69.34 0 top
C399  0.1u/16v_4  [CC0402]  131.53 69.34 90 top
C400  0.1u/16v_4  [CC0402]  136.23 69.21 90 top
C401  10u/6.3v_6  [CC0603]  125.82 68.81 90 top
C402  10u/6.3v_6  [CC0603]  140.3 68.81 90 top
C403  0.1u/16v_4  [CC0402]  127.7 68.7 270 top
C404  10u/6.3v_6  [CC0603]  134.71 68.7 270 top
C405  0.1u/16v_4  [CC0402]  29.68 68.19 0 top
C406  0.1u/16v_4  [CC0402]  29.68 67.05 0 top
C407  0.1u/16v_4  [CC0402]  29.68 66.04 0 top
C408  0.1u/16v_4  [CC0402]  29.68 64.89 0 top
C409  0.01u/50v_4  [CC0402]  20.15 64 0 top
C410  0.1u/16v_4  [CC0402]  27.65 63.75 180 top
C411  0.1u/16v_4  [CC0402]  29.68 63.75 0 top
C412  gs@10u/6.3v_6  [CC0603]  203.54 62.73 270 top
C413  0.01u/50v_4  [CC0402]  25.74 62.23 90 top
C414  4.7u/10v_6  [CC0603]  168.34 61.92 0 top
C415  *0.1u/16v_4  [CC0402]  109.84 60.75 0 top
C416  0.1u/16v_4  [CC0402]  136.23 60.7 270 top
C417  4.7u/10v_6  [CC0603]  168.34 60.6 0 top
C418  10u/6.3v_6  [CC0603]  126 60.47 270 top
C419  10u/6.3v_6  [CC0603]  138.77 60.47 270 top
C420  10u/6.3v_6  [CC0603]  133.64 60.45 90 top
C421  0.1u/16v_4  [CC0402]  132.55 60.45 270 top
C422  0.1u/16v_4  [CC0402]  143.22 60.2 270 top
C423  2.2u/6.3v_6  [CC0603]  141.69 59.94 270 top
C424  1u/6.3v_4  [CC0402]  22.95 59.56 270 top
C425  *22p/50v_4  [CC0402]  209.77 59.56 270 top
C426  1u/6.3v_4  [CC0402]  168.19 59.33 180 top
C427  0.022u/16v_4  [CC0402]  94.58 59.3 0 top
C428  gs@0.1u/16v_4  [CC0402]  197.83 58.29 0 top
C429  1u/6.3v_4  [CC0402]  168.21 58.21 180 top
C430  10u/6.3v_6  [CC0603]  126.05 57.15 90 top
C431  *33p/50v_4  [CC0402]  197.83 57.15 0 top
C432  10u/6.3v_6  [CC0603]  138.34 57.07 90 top
C433  330u/2v_7343  [CC7343]  117.79 56.64 180 top
C434  1u/6.3v_4  [CC0402]  168.19 56.64 180 top
C435  *0.1u/16v_4  [CC0402]  223.74 56.13 270 top
C436  0.01u/50v_4  [CC0402]  224.88 56.13 270 top
C437  0.01u/50v_4  [CC0402]  226.02 56.13 270 top
C438  10u/6.3v_6  [CC0603]  222.47 55.88 270 top
C439  2.2u/6.3v_6  [CC0603]  164.66 55.8 180 top
C440  470p/50v_4  [CC0402]  94.32 55.75 90 top
C441  0.1u/16v_4  [CC0402]  104.51 60.4 180 top
C442  1u/6.3v_4  [CC0402]  168.21 55.45 180 top
C443  2.2u/6.3v_6  [CC0603]  102.2 60.47 0 top
C444  0.1u/16v_4  [CC0402]  132.55 54.99 90 top
C445  10u/6.3v_6  [CC0603]  133.69 54.99 270 top
C446  0.1u/16v_4  [CC0402]  134.84 54.73 90 top
C447  0.1u/16v_4  [CC0402]  136.49 54.73 90 top
C448  0.1u/16v_4  [CC0402]  164.66 54.66 180 top
C449  4.7u/10v_6  [CC0603]  168.16 54.15 0 top
C450  0.1u/16v_4  [CC0402]  15.3 52.57 90 top
C451  470p/50v_4  [CC0402]  16.34 52.57 90 top
C452  100u/6.3v_1206  [CC1206]  21.93 52.57 0 top
C453  *0.1u/16v_4  [CC0402]  226.15 52.57 90 top
C454  *33p/50v_4  [CC0402]  202.02 52.07 90 top
C455  4.7u/10v_6  [CC0603]  168.87 52.17 90 top
C456  *10u/6.3v_4  [CC0402]  38.32 51.68 90 top
C457  *100u/6.3v_3528  [CC3528]  223.99 51.3 90 top
C458  *1.6p/50v_4  [CC0402]  21.3 50.67 180 top
C459  0.1u/16v_4  [CC0402]  26.89 50.67 0 top
C460  *1.6p/50v_4  [CC0402]  21.3 49.4 180 top
C461  0.1u/16v_4  [CC0402]  26.89 49.4 0 top
C462  0.1u/16v_4  [CC0402]  15.2 49.14 270 top
C463  4.7u/10v_6  [CC0603]  168.21 49.04 0 top
C464  0.1u/16v_4  [CC0402]  132.52 47.75 270 top
C465  *0.1u/16v_4  [CC0402]  109.54 47.7 0 top
C466  0.1u/16v_4  [CC0402]  138.72 47.44 270 top
C467  1u/6.3v_4  [CC0402]  165.44 47.24 90 top
C468  1u/6.3v_4  [CC0402]  166.46 47.24 90 top
C469  *1.6p/50v_4  [CC0402]  26.76 47.11 0 top
C470  10u/6.3v_6  [CC0603]  136.28 47.04 90 top
C471  10u/6.3v_6  [CC0603]  126.02 47.01 270 top
C472  10u/6.3v_6  [CC0603]  139.84 46.94 90 top
C473  2.2u/6.3v_6  [CC0603]  142.89 46.63 180 top
C474  0.01u/50v_4  [CC0402]  43.27 46.6 0 top
C475  *1.6p/50v_4  [CC0402]  26.76 45.84 0 top
C476  0.1u/16v_4  [CC0402]  35.52 44.19 270 top
C477  100p/50v_4  [CC0402]  36.54 44.19 90 top
C478  0.022u/16v_4  [CC0402]  138.9 44.07 180 top
C479  470p/50v_4  [CC0402]  142.86 42.39 270 top
C480  0.1u/16v_4  [CC0402]  144.06 42.39 90 top
C481  10u/6.3v_4  [CC0402]  36.03 41.65 180 top
C482  0.1u/16v_4  [CC0402]  207.99 41.78 180 top
C483  1u/10v_4  [CC0402]  24.73 40.64 180 top
C484  10u/6.3v_4  [CC0402]  37.81 40.51 270 top
C485  0.1u/16v_4  [CC0402]  38.82 40.51 270 top
C486  330u/2v_7343  [CC7343]  137.33 40.03 0 top
C487  100u/6.3v_1206  [CC1206]  16.22 40 270 top
C488  10p/50v_4  [CC0402]  35.65 40 180 top
C489  10u/6.3v_4  [CC0402]  26.25 39.87 90 top
C490  *10p/50v_4  [CC0402]  207.99 39.75 0 top
C491  1u/6.3v_4  [CC0402]  206.34 39.37 90 top
C492  0.1u/16v_4  [CC0402]  30.7 38.86 0 top
C493  *22p/50v_4  [CC0402]  32.73 38.86 0 top
C494  *1u/10v_4  [CC0402]  38.82 37.59 90 top
C495  0.1u/16v_4  [CC0402]  195.67 37.33 270 top
C496  0.1u/16v_4  [CC0402]  17.87 37.03 270 top
C497  470p/50v_4  [CC0402]  18.88 37.03 270 top
C498  0.1u/16v_4  [CC0402]  21.93 37.03 90 top
C499  0.1u/16v_4  [CC0402]  22.95 37.03 90 top
C500  0.1u/16v_4  [CC0402]  40.27 36.83 270 top
C501  10u/6.3v_4  [CC0402]  41.29 36.83 270 top
C502  0.1u/16v_4  [CC0402]  16.09 36.65 0 top
C504  0.01u/50v_4  [CC0402]  222.11 36.57 0 top
C505  *1.6p/50v_4  [CC0402]  16.98 35.43 180 top
C507  0.01u/50v_4  [CC0402]  222.11 35.3 0 top
C508  0.1u/16v_4  [CC0402]  209.33 35.15 180 top
C509  0.1u/16v_4  [CC0402]  39.33 34.16 90 top
C510  10u/6.3v_4  [CC0402]  40.35 34.16 90 top
C511  *1.6p/50v_4  [CC0402]  16.98 34.03 180 top
C513  0.01u/50v_4  [CC0402]  221.7 33.52 0 top
C514  0.1u/16v_4  [CC0402]  209.33 33.5 180 top
C515  *10u/6.3v_6  [CC0603]  47.97 33.4 90 top
C516  10u/6.3v_6  [CC0603]  195.67 32.63 270 top
C517  *1.6p/50v_4  [CC0402]  21.55 32.38 90 top
C518  *1.6p/50v_4  [CC0402]  22.69 32.38 90 top
C519  10u/6.3v_4  [CC0402]  26.89 32.25 90 top
C520  10u/6.3v_4  [CC0402]  39.84 32.25 180 top
C522  0.01u/50v_4  [CC0402]  221.7 32.25 0 top
C523  *10u/6.3v_6  [CC0603]  42.38 32.13 180 top
C524  0.1u/16v_4  [CC0402]  39.84 31.24 180 top
C525  *0.1u/16v_4  [CC0402]  49.36 31.11 180 top
C526  *0.1u/16v_4  [CC0402]  42.13 30.98 0 top
C527  10u/6.3v_4  [CC0402]  37.07 29.71 90 top
C528  2.2u/6.3v_4  [CC0402]  38.19 29.71 90 top
C529  10u/6.3v_4  [CC0402]  39.33 29.71 270 top
C530  2.2u/6.3v_4  [CC0402]  35.14 29.21 0 top
C531  4.7u/6.3v_6  [CC0603]  57.62 28.7 0 top
C532  0.1u/16v_4  [CC0402]  26.63 28.57 0 top
C533  0.1u/16v_4  [CC0402]  55.08 28.44 90 top
C534  10u/6.3v_4  [CC0402]  28.92 28.06 90 top
C535  2.2u/6.3v_4  [CC0402]  30.95 27.96 270 top
C536  10u/6.3v_4  [CC0402]  26.63 27.55 0 top
C537  *1000p/50v_4  [CC0402]  41.74 27.43 90 top
C538  *0.1u/16v_4  [CC0402]  43.01 27.43 90 top
C539  0.1u/16v_4  [CC0402]  57.62 27.43 180 top
C540  1u/10v_4  [CC0402]  54.57 26.67 0 top
C541  1u/6.3v_4  [CC0402]  42.25 25.65 0 top
C542  4.7u/6.3v_6  [CC0603]  39.59 25.55 0 top
C543  0.1u/16v_4  [CC0402]  37.05 25.52 0 top
C544  1u/10v_4  [CC0402]  61.81 25.27 90 top
C545  *68p/50v_4  [CC0402]  60.53 15.13 0 top
C546  *68p/50v_4  [CC0402]  63.15 15.13 180 top
C547  100p/50v_4  [CC0402]  15.41 19.55 90 top
C548  *68p/50v_4  [CC0402]  65.36 15.13 180 top
C549  4.7u/6.3v_6  [CC0603]  17.72 17.17 270 top
C550  100p/50v_4  [CC0402]  14.31 17.01 270 top
C551  *68p/50v_4  [CC0402]  67.67 15.16 180 top
C552  4.7u/6.3v_6  [CC0603]  17.72 14.56 90 top
C553  100p/50v_4  [CC0402]  14.08 13.7 90 top
C554  100p/50v_4  [CC0402]  15.13 11.71 0 top
C555  39p/50v_4  [CC0402]  57.49 9.77 270 top
C556  4.7u/10v_6  [CC0603]  62.54 8.77 270 top
C557  dr@0.1u/16v_4  [CC0402]  198.54 192.27 90 bottom
C558  ev@0.1u/16v_4  [CC0402]  199.56 192.27 270 bottom
C559  ev@10u/6.3v_6  [CC0603]  182.26 191.64 270 bottom
C560  dr@4.7u/10v_6  [CC0603]  197.45 191.38 270 bottom
C561  ev@1u/6.3v_4  [CC0402]  180 191.28 90 bottom
C562  ev@0.1u/16v_4  [CC0402]  196.28 191.28 90 bottom
C563  ev@1u/6.3v_4  [CC0402]  189.19 191.26 90 bottom
C564  *120p/50v_4  [CC0402]  190.33 191.26 270 bottom
C565  ev@0.1u/16v_4  [CC0402]  191.48 191.26 270 bottom
C566  ev@0.1u/16v_4  [CC0402]  192.62 191.26 270 bottom
C567  ev@0.1u/16v_4  [CC0402]  193.76 191.26 270 bottom
C568  ev@10u/6.3v_6  [CC0603]  195.03 191.26 270 bottom
C569  dr@1u/6.3v_4  [CC0402]  177.79 191.18 90 bottom
C570  ev@1u/6.3v_4  [CC0402]  178.94 191.18 90 bottom
C571  ev@1u/6.3v_4  [CC0402]  176.64 191.18 90 bottom
C572  ev@1u/6.3v_4  [CC0402]  167.65 189.51 180 bottom
C573  ev@1u/6.3v_4  [CC0402]  167.6 188.03 180 bottom
C574  ev@4.7u/10v_6  [CC0603]  162.19 187.19 270 bottom
C575  dr@0.1u/16v_4  [CC0402]  193.31 186.81 270 bottom
C576  dr@0.1u/16v_4  [CC0402]  194.42 186.79 270 bottom
C577  0.1u/16v_4  [CC0402]  133.31 186.43 270 bottom
C578  1000p/50v_4  [CC0402]  134.33 186.43 270 bottom
C579  ev@1u/6.3v_4  [CC0402]  167.58 186.3 180 bottom
C580  *1u/6.3v_4  [CC0402]  131.15 185.42 270 bottom
C581  *1u/6.3v_4  [CC0402]  132.17 185.42 90 bottom
C582  ev@10u/6.3v_6  [CC0603]  207.63 184.91 180 bottom
C583  ev@0.1u/16v_4  [CC0402]  207.61 183.64 0 bottom
C584  ev@4.7u/10v_6  [CC0603]  202.91 183.51 0 bottom
C585  *120p/50v_4  [CC0402]  207.61 182.49 180 bottom
C586  *120p/50v_4  [CC0402]  168.11 182.22 270 bottom
C587  dr@4.7u/10v_6  [CC0603]  207.86 181.22 180 bottom
C588  ev@0.1u/16v_4  [CC0402]  207.61 180.08 180 bottom
C590  ev@0.01u/25v_4  [CC0402]  203.57 179.65 180 bottom
C592  ev@1u/6.3v_4  [CC0402]  193.31 179.29 90 bottom
C593  dr@1u/6.3v_4  [CC0402]  167.55 178.18 180 bottom
C594  ev@0.1u/16v_4  [CC0402]  167.6 176.93 180 bottom
C595  ev@0.1u/16v_4  [CC0402]  167.63 175.76 0 bottom
C596  dr@10u/6.3v_6  [CC0603]  167.32 174.44 0 bottom
C597  dr@0.1u/16v_4  [CC0402]  167.63 173.2 180 bottom
C598  ev@0.1u/16v_4  [CC0402]  175.09 172.46 0 bottom
C599  ev@0.01u/25v_4  [CC0402]  180.68 171.83 270 bottom
C600  dr@1u/6.3v_4  [CC0402]  196.94 170.43 90 bottom
C601  ev@4.7u/10v_6  [CC0603]  196.94 168.02 90 bottom
C602  ev@4.7u/10v_6  [CC0603]  166.97 167 90 bottom
C603  ev@10u/6.3v_6  [CC0603]  196.94 165.35 90 bottom
C604  dr@0.1u/16v_4  [CC0402]  196.94 162.94 270 bottom
C605  ev@22u/6.3vs_6  [CC0603]  167.35 161.41 90 bottom
C606  *120p/50v_4  [CC0402]  196.43 160.78 270 bottom
C607  ev@0.22u/10v_4  [CC0402]  167.73 159.25 180 bottom
C608  ev@0.1u/16v_4  [CC0402]  196.43 158.75 270 bottom
C609  ev@0.22u/10v_4  [CC0402]  167.73 158.24 180 bottom
C610  ev@0.22u/10v_4  [CC0402]  167.73 157.11 180 bottom
C611  ev@1u/6.3v_4  [CC0402]  198.59 156.71 270 bottom
C612  ev@0.1u/16v_4  [CC0402]  199.73 156.71 90 bottom
C613  ev@0.1u/16v_4  [CC0402]  200.88 156.71 270 bottom
C614  dr@0.1u/16v_4  [CC0402]  202.02 156.71 90 bottom
C615  ev@1u/6.3v_4  [CC0402]  203.16 156.71 270 bottom
C616  ev@0.1u/16v_4  [CC0402]  205.7 156.71 270 bottom
C617  ev@1u/6.3v_4  [CC0402]  206.84 156.71 270 bottom
C618  dr@0.1u/16v_4  [CC0402]  211.54 156.71 270 bottom
C619  ev@0.1u/16v_4  [CC0402]  212.69 156.71 270 bottom
C620  ev@0.1u/16v_4  [CC0402]  213.83 156.71 270 bottom
C621  ev@0.1u/16v_4  [CC0402]  214.97 156.71 270 bottom
C622  ev@1u/6.3v_4  [CC0402]  216.12 156.71 270 bottom
C623  ev@1u/6.3v_4  [CC0402]  217.26 156.71 270 bottom
C624  ev@0.1u/16v_4  [CC0402]  218.4 156.71 90 bottom
C625  ev@10u/6.3v_6  [CC0603]  204.43 156.33 90 bottom
C626  ev@0.22u/10v_4  [CC0402]  167.73 156.1 180 bottom
C627  ev@0.22u/10v_4  [CC0402]  167.73 154.94 180 bottom
C628  0.1u/16v_4  [CC0402]  161.89 154.05 180 bottom
C629  ev@0.22u/10v_4  [CC0402]  167.73 153.92 180 bottom
C630  ev@4.7u/10v_6  [CC0603]  213.32 153.03 270 bottom
C631  ev@4.7u/10v_6  [CC0603]  215.35 153.03 270 bottom
C632  ev@0.22u/10v_4  [CC0402]  167.73 152.78 180 bottom
C633  dr@1u/6.3v_4  [CC0402]  199.1 152.78 270 bottom
C634  ev@0.1u/16v_4  [CC0402]  200.24 152.78 270 bottom
C635  ev@0.1u/16v_4  [CC0402]  201.38 152.78 270 bottom
C636  ev@1u/6.3v_4  [CC0402]  202.53 152.78 270 bottom
C637  dr@0.1u/16v_4  [CC0402]  203.67 152.78 270 bottom
C638  ev@0.22u/10v_4  [CC0402]  167.73 151.76 180 bottom
C639  ev@10p/50v_4  [CC0402]  198.02 148.93 90 bottom
C641  10u/6.3v_4  [CC0402]  154.14 147.06 90 bottom
C642  10u/6.3v_4  [CC0402]  155.16 147.06 90 bottom
C643  10u/6.3v_4  [CC0402]  156.17 147.06 90 bottom
C644  ev@10p/50v_4  [CC0402]  198.02 146.89 270 bottom
C645  47u/6.3v_8  [CC0805]  143.09 145.03 0 bottom
C647  10u/6.3v_4  [CC0402]  136.99 141.35 0 bottom
C648  0.1u/16v_4  [CC0402]  145 141.09 270 bottom
C649  0.1u/16v_4  [CC0402]  146.01 141.09 270 bottom
C650  47u/6.3v_8  [CC0805]  142.76 140.97 0 bottom
C651  10u/6.3v_4  [CC0402]  136.99 140.33 0 bottom
C652  ev@0.22u/10v_4  [CC0402]  152.23 136.39 90 bottom
C653  ev@0.22u/10v_4  [CC0402]  153.25 136.39 270 bottom
C654  ev@0.22u/10v_4  [CC0402]  145.38 139.06 90 bottom
C655  ev@0.22u/10v_4  [CC0402]  153.35 138.48 90 bottom
C656  ev@0.22u/10v_4  [CC0402]  154.37 138.48 90 bottom
C657  10u/6.3v_4  [CC0402]  136.99 139.31 0 bottom
C658  10p/50v_4  [CC0402]  133.44 139.19 90 bottom
C659  47u/6.3v_8  [CC0805]  142.2 138.93 0 bottom
C660  ev@0.22u/10v_4  [CC0402]  146.39 139.06 90 bottom
C661  ev@0.22u/10v_4  [CC0402]  151.09 138.48 90 bottom
C662  ev@0.22u/10v_4  [CC0402]  152.11 138.48 90 bottom
C663  10u/6.3v_4  [CC0402]  136.99 138.3 0 bottom
C664  10u/6.3v_4  [CC0402]  136.99 137.28 0 bottom
C665  10p/50v_4  [CC0402]  133.44 137.16 270 bottom
C666  47u/6.3v_8  [CC0805]  142.2 136.9 0 bottom
C667  10u/6.3v_4  [CC0402]  137.02 136.27 0 bottom
C668  0.1u/16v_4  [CC0402]  145.66 136.27 270 bottom
C669  0.1u/16v_4  [CC0402]  146.67 136.27 270 bottom
C670  *short_4  [SHORT0402]  115.3 135.76 90 bottom
C671  *short_4  [SHORT0402]  116.42 135.76 90 bottom
C672  1u/6.3v_4  [CC0402]  155.41 134.23 180 bottom
C673  10u/6.3v_4  [CC0402]  137.02 135.25 0 bottom
C674  10u/6.3v_4  [CC0402]  142.07 135.25 180 bottom
C675  10u/6.3v_4  [CC0402]  133.95 135 270 bottom
C676  10u/6.3v_4  [CC0402]  135.09 135 270 bottom
C677  1u/6.3v_4  [CC0402]  147.56 134.62 0 bottom
C678  10u/6.3v_4  [CC0402]  137.02 134.23 0 bottom
C679  10u/6.3v_4  [CC0402]  142.07 134.23 180 bottom
C680  *1u/6.3v_4  [CC0402]  155.41 134.23 180 top
C681  gt3@1u/6.3v_2  [CC0201]  105.5 130.93 0 bottom
C682  gt3@10u/6.3v_4  [CC0402]  108.29 130.42 180 bottom
C683  gt3@1u/6.3v_2  [CC0201]  105.5 129.92 0 bottom
C684  gt3@1u/6.3v_2  [CC0201]  105.5 128.9 0 bottom
C685  gt3@1u/6.3v_2  [CC0201]  108.55 128.77 180 bottom
C686  gt3@10u/6.3v_4  [CC0402]  109.94 128.52 90 bottom
C687  gt3@10u/6.3v_4  [CC0402]  110.96 128.52 90 bottom
C688  gt3@1u/6.3v_2  [CC0201]  105.5 127.88 0 bottom
C689  gt3@1u/6.3v_2  [CC0201]  108.55 127.76 180 bottom
C690  47u/6.3v_8  [CC0805]  106.13 126.36 180 bottom
C691  22u/6.3v_6  [CC0603]  108.42 125.73 90 bottom
C692  22u/6.3v_6  [CC0603]  109.92 125.73 90 bottom
C693  22u/6.3v_6  [CC0603]  111.11 125.73 90 bottom
C694  22u/6.3v_6  [CC0603]  112.28 125.73 90 bottom
C695  1u/6.3v_4  [CC0402]  160.01 124.58 90 bottom
C696  47u/6.3v_8  [CC0805]  106.13 124.35 180 bottom
C697  47u/6.3v_8  [CC0805]  106.77 122.35 180 bottom
C698  1u/6.3v_4  [CC0402]  160.97 122.55 180 bottom
C699  47u/6.3v_8  [CC0805]  155.97 137.79 90 bottom
C700  1u/6.3v_4  [CC0402]  102.83 122.8 90 bottom
C701  1u/6.3v_4  [CC0402]  101.18 121.79 90 bottom
C702  47u/6.3v_8  [CC0805]  106.77 120.34 180 bottom
C703  22u/6.3v_6  [CC0603]  109.05 120.26 270 bottom
C704  22u/6.3v_6  [CC0603]  110.32 120.26 270 bottom
C705  22u/6.3v_6  [CC0603]  111.59 120.26 270 bottom
C706  22u/6.3v_6  [CC0603]  112.86 120.26 270 bottom
C707  22u/6.3v_6  [CC0603]  107.78 118.36 0 bottom
C708  gt3@10u/6.3v_4  [CC0402]  109.69 117.6 270 bottom
C709  gt3@10u/6.3v_4  [CC0402]  110.71 117.6 270 bottom
C710  1u/6.3v_4  [CC0402]  100.93 117.09 270 bottom
C711  1u/6.3v_4  [CC0402]  102.2 117.09 270 bottom
C712  1u/6.3v_4  [CC0402]  161.76 116.28 180 bottom
C713  0.1u/16v_4  [CC0402]  16.47 113.79 180 bottom
C714  *10p/50v_4  [CC0402]  10.5 113.66 270 bottom
C715  10u/6.3v_6  [CC0603]  24.09 113.31 0 bottom
C716  10p/50v_4  [CC0402]  11.01 112.14 0 bottom
C717  0.1u/16v_4  [CC0402]  22.26 111.71 270 bottom
C718  10p/50v_4  [CC0402]  11.01 110.99 0 bottom
C719  *.01u/50v_4  [CC0402]  68.03 112.39 90 top
C720  0.1u/16v_4  [CC0402]  13.7 110.16 180 bottom
C721  0.01u/50v_4  [CC0402]  227.8 110.1 0 bottom
C722  0.1u/16v_4  [CC0402]  24.47 109.85 0 bottom
C723  2.2u_6  [CC0603]  64.22 109.85 270 top
C724  *10p/50v_4  [CC0402]  10.5 109.22 90 bottom
C725  0.1u/16v_4  [CC0402]  19.39 109.22 0 bottom
C726  0.01u/50v_4  [CC0402]  227.8 109.09 0 bottom
C727  *0.1u/16v_4  [CC0402]  24.47 108.83 0 bottom
C728  .01u/50v_4  [CC0402]  65.49 110.1 270 top
C729  0.1u/16v_4  [CC0402]  19.39 108.2 0 bottom
C730  *0.1u/16v_4  [CC0402]  227.8 108.07 0 bottom
C731  0.1u/16v_4  [CC0402]  190.94 108 180 bottom
C732  0.1u/16v_4  [CC0402]  162.01 107.69 180 bottom
C733  *0.1u/16v_4  [CC0402]  227.8 107.06 0 bottom
C734  4.7u/10v_6  [CC0603]  19.39 106.98 180 bottom
C735  0.1u/16v_4  [CC0402]  190.94 106.98 180 bottom
C736  0.1u/16v_4  [CC0402]  24.47 106.8 0 bottom
C737  10u/6.3v_6  [CC0603]  227.8 105.91 0 bottom
C738  0.1u/16v_4  [CC0402]  19.42 105.81 0 bottom
C739  *10p/50v_4  [CC0402]  146.14 104.26 90 bottom
C740  *100u/6.3v_3528  [CC3528]  226.91 103.63 0 bottom
C741  *4m@0.1u/16v_4  [CC0402]  174.1 102.38 180 bottom
C742  *10p/50v_4  [CC0402]  148.3 101.09 0 bottom
C743  0.01u/50v_4  [CC0402]  227.85 99.46 0 bottom
C744  0.01u/50v_4  [CC0402]  227.85 98.45 0 bottom
C745  *22p/50v_4  [CC0402]  177.38 98.29 0 bottom
C746  1000p/3kv_1808  [CC1808]  25.49 97.15 0 bottom
C747  *22p/50v_4  [CC0402]  177.38 97.02 180 bottom
C748  1u/6.3v_4  [CC0402]  161 97.13 180 bottom
C749  0.01u/50v_4  [CC0402]  227.98 96.41 0 bottom
C750  *0.1u/16v_4  [CC0402]  153.38 96.39 180 bottom
C751  0.01u/50v_4  [CC0402]  227.98 95.4 0 bottom
C752  ioac@0.1u/25v_6  [CC0603]  216.24 94.23 0 bottom
C753  0.1u/16v_4  [CC0402]  191.86 90.04 180 bottom
C754  0.1u/16v_4  [CC0402]  171.67 89.78 0 bottom
C755  0.1u/16v_4  [CC0402]  191.86 89.02 180 bottom
C756  **ioac@1000p/50v_4  [CC0402]  177.13 88.51 90 bottom
C757  0.1u/16v_4  [CC0402]  38.06 88.13 0 bottom
C758  *1u/6.3v_4  [CC0402]  38.06 87.12 0 bottom
C759  **ioac@0.1u/16v_4  [CC0402]  173.82 86.74 180 bottom
C760  0.1u/16v_4  [CC0402]  33.49 86.61 180 bottom
C761  *0.1u/16v_4  [CC0402]  38.06 86.1 0 bottom
C762  0.1u/16v_4  [CC0402]  31.97 84.83 0 bottom
C763  *0.1u/16v_4  [CC0402]  196.05 83.43 90 bottom
C764  *0.1u/16v_4  [CC0402]  218.53 78.61 0 bottom
C765  *0.1u/25v_6  [CC0603]  211.8 76.96 0 bottom
C766  tpm@0.1u/16v_4  [CC0402]  213.32 58.42 270 bottom
C767  tpm@10u/6.3v_6  [CC0603]  211.42 58.03 0 bottom
C768  tpm@0.1u/16v_4  [CC0402]  218.53 57.91 180 bottom
C769  0.1u/16v_4  [CC0402]  197.19 49.14 270 bottom
C770  0.1u/16v_4  [CC0402]  200.62 49.14 270 bottom
C771  0.1u/16v_4  [CC0402]  204.05 49.14 270 bottom
C772  0.1u/16v_4  [CC0402]  206.59 49.14 270 bottom
C773  0.1u/16v_4  [CC0402]  73.62 17.42 180 bottom
C774  tpm@0.1u/16v_4  [CC0402]  217.64 46.6 90 bottom
C775  tpm@0.1u/16v_4  [CC0402]  214.97 45.97 90 bottom
C776  tpm@10u/6.3v_6  [CC0603]  213.7 45.72 90 bottom
C777  0.1u/16v_4  [CC0402]  189.93 43.07 90 bottom
C778  0.1u/16v_4  [CC0402]  210.45 42.29 180 bottom
C779  1u/6.3v_4  [CC0402]  212.56 29.08 180 bottom
C780  0.1u/16v_4  [CC0402]  200.27 27.78 180 bottom
C781  0.1u/16v_4  [CC0402]  208.37 26.54 90 bottom
C782  100u/6.3v_1206  [CC1206]  213.42 25.65 90 bottom
C783  0.1u/16v_4  [CC0402]  204.03 23.54 180 bottom
C785  0.1u/16v_4  [CC0402]  193.26 22.35 0 bottom
C786  *1000p/50v_4  [CC0402]  208.88 22.09 180 bottom
C787  *0.1u/16v_4  [CC0402]  204.18 22.02 90 bottom
C788  *0.1u/16v_4  [CC0402]  205.19 22.02 90 bottom
C789  10u/6.3v_6  [CC0603]  213.32 21.97 0 bottom
C790  0.22u/25v_6  [CC0603]  199.99 20.82 0 bottom
C791  0.1u/16v_4  [CC0402]  213.8 20.87 180 bottom
C792  470p/50v_4  [CC0402]  213.8 19.83 180 bottom
C793  1u/6.3v_4  [CC0402]  161.66 125.85 0 bottom
C794  *1u/6.3v_4  [CC0402]  164.99 118.49 0 bottom
C796  180p/50v_4  [CC0402]  207.99 17.52 270 top
C797  180p/50v_4  [CC0402]  179.59 119.6 90 top
C798  180p/50v_4  [CC0402]  191.86 95.12 180 bottom
C799  180p/50v_4  [CC0402]  225.64 112.14 0 top
C800  180p/50v_4  [CC0402]  143.47 191.26 270 bottom
C801  180p/50v_4  [CC0402]  114.52 181.73 90 top
C802  180p/50v_4  [CC0402]  228.05 105.53 0 top
C803  180p/50v_4  [CC0402]  147.28 197.61 0 bottom
C804  180p/50v_4  [CC0402]  135.98 186.3 180 bottom
C805  180p/50v_4  [CC0402]  142.63 16.15 90 bottom
C806  0.1u/16v_4  [CC0402]  166.56 96.06 180 top
C807  tpm@33p/50v_4  [CC0402]  220.94 46.6 270 bottom
C808  0.1u/16v_4  [CC0402]  194.55 89.94 180 top
C809  0.01u/50v_4  [CC0402]  225.39 27.3 180 top
C810  0.01u/50v_4  [CC0402]  72.22 20.57 90 top
C811  0.1u/16v_4  [CC0402]  219.54 22.47 90 top
C812  *0.1u/16v_4  [CC0402]  54.19 9.65 270 top
C813  0.1u/16v_4  [CC0402]  54.19 13.46 270 top
C814  1000p/50v_4  [CC0402]  110.45 138.68 90 bottom
C815  *1000p/50v_4  [CC0402]  154.01 189.61 180 top
C816  *1000p/50v_4  [CC0402]  160.62 153.03 0 bottom
C817  *1000p/50v_4  [CC0402]  112.1 181.1 180 bottom
C818  *1000p/50v_4  [CC0402]  138.9 200.27 0 bottom
C819  *1000p/50v_4  [CC0402]  113.25 146.68 180 bottom
CN2  *aces_88511-180n  [88511-180N-18P-L]  180.43 83.46 90 top
CN3  *uart function  [88513-0601-6P-L-SMT]  153.38 79.88 270 top
CN4  sd-card  [SDCARD-PSDAT4-09GLBS1NN4H0-11P]  33.89 20.9 0 top
CN5  50398-04071-001  [GS12401-1011-40P-R-NH-SMT]  134.76 192.82 35 bottom
CN6  kbl@kb_backlight  [50503-0040N-V01-4P-L]  210.74 139.75 270 bottom
CN7  crt conn  [DSUB-070546FR015S265ZR-15P-V]  4.09 113.3 270 bottom
CN8  fan_3p  [HS8803F-3P-L]  63.27 111.85 90 bottom
CN9  6030d-13g20  [SATA-SLS-13PVAB-13P-R]  233.48 103.51 270 bottom
CN10  wlan_ngff conn(type 2230)  [NGFF-APCI0085-P005A-75P-KE]  185.39 99.48 270 bottom
CN11  lan_rj45  [RJ45-130452-01-8P-RUV]  6.22 86.79 90 bottom
CN12  hdmi connector  [HDMI-10444-19001-19P]  2.45 67.7 90 bottom
CN13  usb3.0 conn  [USB-2UB4029-200201F-9P-SMT]  2.91 47.7 90 bottom
CN14  hdd conn  [SATA-C166FQ-12208-L-22P-R]  227.89 47.6 270 bottom
CN16  usb3.0 conn  [USB-2UB4029-200201F-9P-SMT]  2.91 29.7 90 bottom
CN17  tp cn  [88513-0801-8P-L]  205.54 19.85 180 bottom
CN18  spk_conn_4p  [50224-00401-001-4P-L]  63.89 17.32 0 bottom
CN20  kb conn  [50584-0280N-V01-28P-L]  163.29 15.4 180 bottom
CN21  2sj3080-077111f  [PHJK-2SJ3080-077111F-6P]  2.82 14.88 90 bottom
CN22  usb2.0 db  [88511-10XX-10P-L]  219.02 18.7 270 bottom
CP1  *220p_8p4r  [8P4R]  169.13 24.38 180 bottom
CP2  *220p_8p4r  [8P4R]  172.81 24.38 180 bottom
CP3  *220p_8p4r  [8P4R]  176.49 24.38 180 bottom
CP4  *220p_8p4r  [8P4R]  180.3 24.38 180 bottom
CP5  *220p_8p4r  [8P4R]  183.98 24.38 180 bottom
CP6  *220p_8p4r  [8P4R]  187.79 24.38 180 bottom
D1  1n4148ws  [DSM]  114.77 178.43 270 top
D2  tvs/6pf_4  [CC0402]  205.7 92.45 270 top
D3  tvs/6pf_4  [CC0402]  210.91 87.75 180 top
D4  *tvs/6pf_4  [CC0402]  79.97 79.37 90 top
D5  *tvs/6pf_4  [CC0402]  82 79.37 90 top
D6  *az5125-01j  [RC0402]  15.07 74.72 270 top
D7  bat54c  [SOT323_213-2_1-1_3-2N7002W]  83.65 72.13 0 top
D8  gs@rb500v-40  [DSM]  208.24 58.67 270 top
D9  1n4148ws  [DSM]  39.59 49.02 0 top
D10  1n4148ws  [DSM]  39.59 46.99 0 top
